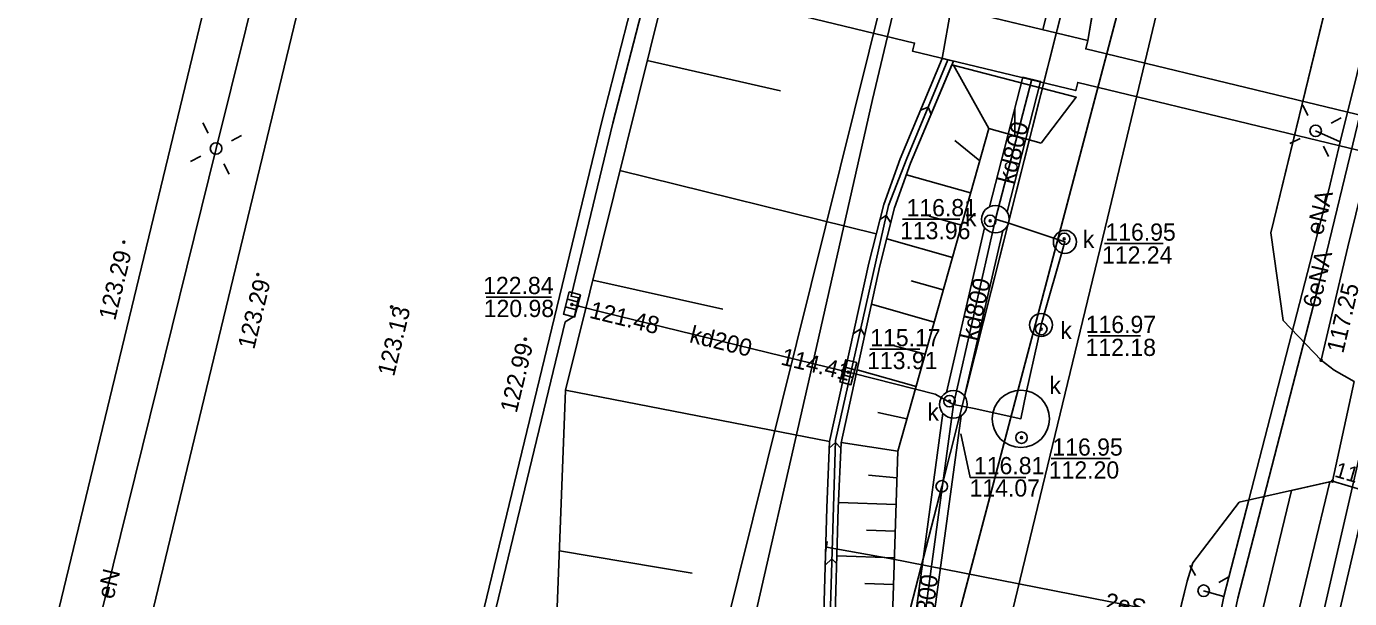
# Model space of a CAD drawing. Extents: x 6424617 to 6425697, y 5665845 to 5667190.
# Drawn here: x 6425313.5 to 6425371.2, y 5666362.7 to 5666387.6 of the extents above; entities that cross this region are included whole.
import ezdxf

# ---------------------------------------------------------------- set-up
doc = ezdxf.new("R2010")
doc.units = 0
for name, color, linetype in [('Warstwa 1', 7, 'Continuous'), ('Warstwa 10', 7, 'Continuous'), ('Warstwa 11', 7, 'Continuous'), ('Warstwa 12', 7, 'Continuous'), ('Warstwa 13', 7, 'Continuous'), ('Warstwa 14', 7, 'Continuous'), ('Warstwa 15', 7, 'Continuous'), ('Warstwa 16', 7, 'Continuous'), ('Warstwa 2', 7, 'Continuous'), ('Warstwa 20', 7, 'Continuous'), ('Warstwa 21', 7, 'Continuous'), ('Warstwa 22', 7, 'Continuous'), ('Warstwa 25', 7, 'Continuous'), ('Warstwa 4', 7, 'Continuous'), ('Warstwa 5', 7, 'Continuous'), ('Warstwa 6', 7, 'Continuous'), ('Warstwa 61', 7, 'Continuous'), ('Warstwa 8', 7, 'Continuous'), ('Warstwa 9', 7, 'Continuous')]:
    doc.layers.add(name, color=color, linetype=linetype)

msp = doc.modelspace()

# ---------------------------------------------------------------- linework, layer by layer
at = {"layer": 'Warstwa 1'}
for p, q in [((6425353.441, 5666367.596), (6425363.818, 5666408.694)), ((6425353.441, 5666367.596), (6425363.818, 5666408.694)), ((6425352.06, 5666353.98), (6425364.93, 5666402.71)), ((6425352.06, 5666353.98), (6425364.93, 5666402.71)), ((6425328.388, 5666270.5), (6425353.441, 5666367.596)), ((6425328.388, 5666270.5), (6425353.441, 5666367.596))]:
    msp.add_line(p, q, dxfattribs=at)
at = {"layer": 'Warstwa 10'}
msp.add_lwpolyline([(6425441.845, 5666345.034), (6425435.644, 5666345.684), (6425416.754, 5666350.792), (6425414.426, 5666349.31), (6425409.689, 5666350.497), (6425397.042, 5666354.07), (6425390.053, 5666355.924), (6425382.597, 5666357.904), (6425376.603, 5666359.336), (6425374.869, 5666359.807), (6425368.783, 5666361.001), (6425351.183, 5666364.453), (6425348.415, 5666364.948)], dxfattribs=at)
msp.add_circle((6425353.441, 5666367.596), 0.25, dxfattribs=at)
msp.add_circle((6425353.441, 5666367.596), 0.25, dxfattribs=at)
at = {"layer": 'Warstwa 12'}
for points in [[(6425398.761, 5666563.583), (6425397.55, 5666559.5), (6425397.03, 5666557.16), (6425392.45, 5666536.96), (6425386, 5666508.09), (6425382.01, 5666490.27), (6425381.21, 5666479.99), (6425379.9, 5666475.3), (6425381.52, 5666474.89), (6425375.93, 5666454.14), (6425373.99, 5666454.38), (6425373.44, 5666451.82), (6425375.23, 5666451.4), (6425362.43, 5666401.17), (6425355.8, 5666402.66), (6425355.08, 5666402.04), (6425351.66, 5666389.66), (6425350.42, 5666384.46), (6425347.89, 5666373.29), (6425344.69, 5666359.22), (6425346.02, 5666355.28), (6425340.77, 5666330.04), (6425337.023, 5666314.31)], [(6425305.48, 5666314.773), (6425311.14, 5666338.26), (6425315.72, 5666356.59), (6425314.85, 5666358.59), (6425315.59, 5666360.88), (6425316.68, 5666361.57), (6425321.81, 5666382.32), (6425327.66, 5666405.82), (6425332.54, 5666426.33), (6425338.92, 5666452.89), (6425344.68, 5666476.52), (6425348.06, 5666490.52), (6425353.32, 5666512.48), (6425356.9, 5666527.18)], [(6425366.353, 5666362.72), (6425369.879, 5666376.399), (6425373.51, 5666391.396), (6425377.162, 5666406.423), (6425378.544, 5666412.437), (6425386.549, 5666444.283), (6425388.297, 5666450.692), (6425392.281, 5666465.105), (6425394.427, 5666468.919), (6425394.601, 5666469.247), (6425394.673, 5666469.407), (6425394.808, 5666469.795), (6425394.976, 5666470.533), (6425395.345, 5666472.079), (6425395.789, 5666472.383), (6425396.66, 5666472.55), (6425396.753, 5666472.692)], [(6425357.852, 5666387.491), (6425359.23, 5666393.09)], [(6425372.286, 5666388.56), (6425370.814, 5666382.608), (6425370.308, 5666380.514), (6425366.825, 5666367.005), (6425365.734, 5666362.797), (6425363.15, 5666350.048), (6425362.095, 5666344.63), (6425362.071, 5666344.32), (6425362.257, 5666343.998), (6425365.292, 5666341.111), (6425367.972, 5666338.599), (6425368.306, 5666338.48)], [(6425355.522, 5666379.782), (6425356.973, 5666385.427), (6425357.751, 5666385.24), (6425356.289, 5666379.557)], [(6425369.739, 5666383.091), (6425370.814, 5666382.608)], [(6425353.95, 5666371.17), (6425354.85, 5666370.99), (6425356.89, 5666370.54), (6425357.12, 5666371.67), (6425357.63, 5666373.94), (6425357.77, 5666374.63), (6425357.97, 5666375.3), (6425358.62, 5666377.58), (6425358.81, 5666378.25), (6425358.15, 5666378.47), (6425356.45, 5666379.04), (6425355.78, 5666379.24)], [(6425353.651, 5666371.69), (6425355.31, 5666378.867)], [(6425356.101, 5666378.733), (6425354.435, 5666371.523)], [(6425337.32, 5666375.52), (6425337.57, 5666375.46), (6425338.72, 5666375.17), (6425349.12, 5666372.63), (6425349.37, 5666372.57), (6425349.61, 5666372.51), (6425353.15, 5666371.62), (6425353.95, 5666371.17)], [(6425362.024, 5666327.189), (6425372.889, 5666374.253)], [(6425351.71, 5666357.654), (6425353.494, 5666370.78)], [(6425354.286, 5666370.673), (6425352.503, 5666357.553)], [(6425365.734, 5666362.797), (6425364.857, 5666363.048)], [(6425368.46, 5666338.433), (6425362.583, 5666344.464), (6425364.475, 5666353.762), (6425366.353, 5666362.72)]]:
    msp.add_lwpolyline(points, dxfattribs=at)
at = {"layer": 'Warstwa 14'}
for p, q in [((6425354.229, 5666379.242), (6425351.726, 5666379.242)), ((6425363.087, 5666378.178), (6425360.53, 5666378.178)), ((6425336.427, 5666375.838), (6425333.589, 5666375.838)), ((6425362.109, 5666374.154), (6425359.818, 5666374.154)), ((6425352.486, 5666373.58), (6425350.305, 5666373.58)), ((6425360.788, 5666368.81), (6425358.208, 5666368.81))]:
    msp.add_line(p, q, dxfattribs=at)
msp.add_lwpolyline([(6425357.102, 5666367.98), (6425354.687, 5666367.98), (6425354.278, 5666369.881)], dxfattribs=at)
for centre in [(6425355.55, 5666379.17), (6425358.78, 5666378.38), (6425337.32, 5666375.52), (6425337.57, 5666375.46), (6425357.78, 5666374.45), (6425349.12, 5666372.63), (6425349.37, 5666372.57), (6425353.78, 5666371.31), (6425356.92, 5666369.72)]:
    msp.add_circle(centre, 0.045, dxfattribs=at)
at = {"layer": 'Warstwa 16'}
for centre, radius in [((6425355.78, 5666379.24), 0.6), ((6425358.81, 5666378.25), 0.5), ((6425357.77, 5666374.63), 0.5), ((6425353.95, 5666371.17), 0.6), ((6425356.89, 5666370.54), 1.25)]:
    msp.add_circle(centre, radius, dxfattribs=at)
at = {"layer": 'Warstwa 2'}
msp.add_lwpolyline([(6425342.431, 5666314.245), (6425342.9, 5666316.26), (6425351.432, 5666353.898), (6425342.677, 5666355.997), (6425354.705, 5666404.396), (6425364.488, 5666402.728), (6425382.828, 5666478.302), (6425401.605, 5666563.549)], dxfattribs=at)
for centre in [(6425369.739, 5666383.091), (6425321.81, 5666382.32), (6425364.857, 5666363.048)]:
    msp.add_circle(centre, 0.25, dxfattribs=at)
at = {"layer": 'Warstwa 20'}
msp.add_line((6425348.38, 5666364.7), (6425348.45, 5666365.196), dxfattribs=at)
for points in [[(6425326.04, 5666314.442), (6425336.507, 5666357.769), (6425337.041, 5666371.794), (6425341.788, 5666390.934), (6425346.79, 5666410.35), (6425362.358, 5666467.618), (6425366.796, 5666476.821), (6425368.004, 5666481.671), (6425368.42, 5666492.007), (6425372.53, 5666509.068), (6425385.231, 5666561.556), (6425385.761, 5666563.74)], [(6425357.772, 5666382.553), (6425355.492, 5666383.194), (6425351.527, 5666369.131), (6425351.075, 5666355.185), (6425350.421, 5666351.646), (6425344.982, 5666329.077), (6425341.427, 5666314.257)]]:
    msp.add_lwpolyline(points, dxfattribs=at)
at = {"layer": 'Warstwa 21'}
for points in [[(6425338.781, 5666314.289), (6425342.093, 5666328.629), (6425347.916, 5666354.162), (6425348.109, 5666355.419), (6425348.432, 5666366.657), (6425348.554, 5666369.545), (6425350.265, 5666377.317), (6425350.911, 5666379.876), (6425351.627, 5666381.874), (6425353.464, 5666386.247), (6425353.858, 5666388.451), (6425354.565, 5666392.214), (6425355.215, 5666394.983), (6425357.587, 5666405.034), (6425362.218, 5666424.397), (6425369.236, 5666451.879), (6425372.67, 5666465.301), (6425376.112, 5666474.212), (6425378.491, 5666484.102), (6425377.911, 5666489.644), (6425387.002, 5666528.883), (6425394.525, 5666561.078), (6425395.128, 5666563.627)], [(6425359.81, 5666387.02), (6425354.35, 5666388.333), (6425355.063, 5666392.105), (6425355.693, 5666394.875), (6425357.414, 5666402.106), (6425358.065, 5666404.925), (6425362.696, 5666424.268), (6425369.714, 5666451.75), (6425373.147, 5666465.152), (6425376.589, 5666474.063), (6425378.991, 5666484.073), (6425378.41, 5666489.615), (6425387.48, 5666528.774), (6425395.003, 5666560.949), (6425395.635, 5666563.62)], [(6425339.288, 5666314.283), (6425342.571, 5666328.52), (6425348.415, 5666354.073), (6425348.608, 5666355.37), (6425348.932, 5666366.648), (6425349.053, 5666369.496), (6425350.743, 5666377.208), (6425351.388, 5666379.727), (6425352.084, 5666381.686), (6425353.882, 5666385.964), (6425359.308, 5666384.556)]]:
    msp.add_lwpolyline(points, dxfattribs=at)
at = {"layer": 'Warstwa 22'}
msp.add_lwpolyline([(6425352.7, 5666388.73), (6425359.81, 5666387.02), (6425359.721, 5666386.659), (6425384.611, 5666380.644), (6425384.259, 5666379.186), (6425359.369, 5666385.201), (6425359.28, 5666384.84), (6425352.17, 5666386.56), (6425352.257, 5666386.916), (6425297.227, 5666400.216), (6425297.583, 5666401.674), (6425352.613, 5666388.374), (6425352.7, 5666388.73)], dxfattribs=at)
at = {"layer": 'Warstwa 25'}
for centre in [(6425317.791, 5666378.234), (6425323.627, 5666376.828), (6425329.464, 5666375.412), (6425335.29, 5666374.006), (6425369.98, 5666373.09), (6425370.47, 5666367.82)]:
    msp.add_circle(centre, 0.045, dxfattribs=at)
at = {"layer": 'Warstwa 4'}
for p, q in [((6425337.607, 5666375.624), (6425337.124, 5666375.754)), ((6425337.516, 5666375.286), (6425337.033, 5666375.416)), ((6425349.656, 5666372.676), (6425349.173, 5666372.803)), ((6425349.567, 5666372.337), (6425349.084, 5666372.464))]:
    msp.add_line(p, q, dxfattribs=at)
for points in [[(6425369.403, 5666383.762), (6425369.179, 5666384.209)], [(6425321.469, 5666382.988), (6425321.241, 5666383.433)], [(6425370.41, 5666383.427), (6425370.857, 5666383.651)], [(6425322.478, 5666382.661), (6425322.923, 5666382.889)], [(6425369.068, 5666382.755), (6425368.621, 5666382.531)], [(6425370.075, 5666382.42), (6425370.299, 5666381.973)], [(6425321.142, 5666381.979), (6425320.697, 5666381.751)], [(6425322.151, 5666381.652), (6425322.379, 5666381.207)], [(6425364.497, 5666363.706), (6425364.256, 5666364.144)], [(6425365.515, 5666363.408), (6425365.953, 5666363.649)]]:
    msp.add_lwpolyline(points, dxfattribs=at)
for points in [[(6425337.692, 5666375.938), (6425337.431, 5666374.972), (6425336.948, 5666375.102), (6425337.209, 5666376.068)], [(6425349.739, 5666372.99), (6425349.485, 5666372.023), (6425349.001, 5666372.15), (6425349.255, 5666373.117)]]:
    msp.add_lwpolyline(points, close=True, dxfattribs=at)
for centre in [(6425355.55, 5666379.17), (6425358.78, 5666378.38), (6425357.78, 5666374.45), (6425353.78, 5666371.31), (6425356.92, 5666369.72)]:
    msp.add_circle(centre, 0.25, dxfattribs=at)
at = {"layer": 'Warstwa 5'}
for p, q in [((6425364.91, 5666345.22), (6425370.351, 5666367.793)), ((6425370.351, 5666367.793), (6425370.47, 5666367.82)), ((6425370.47, 5666367.82), (6425381.83, 5666364.46))]:
    msp.add_line(p, q, dxfattribs=at)
at = {"layer": 'Warstwa 6'}
for points in [[(6425305.245, 5666173.41), (6425312.278, 5666201.804), (6425314.518, 5666211.716), (6425317.57, 5666225.189), (6425322.489, 5666245.769), (6425323.828, 5666251.474), (6425324.47, 5666254.176), (6425328.388, 5666270.5), (6425353.441, 5666367.596), (6425363.818, 5666408.694)], [(6425363.818, 5666408.694), (6425353.441, 5666367.596), (6425328.388, 5666270.5), (6425324.47, 5666254.176), (6425323.828, 5666251.474), (6425322.489, 5666245.769), (6425317.57, 5666225.189), (6425314.518, 5666211.716), (6425312.278, 5666201.804), (6425305.245, 5666173.41)], [(6425306.64, 5666159.22), (6425325.89, 5666241.74), (6425352.06, 5666353.98), (6425364.93, 5666402.71)], [(6425364.93, 5666402.71), (6425352.06, 5666353.98), (6425325.89, 5666241.74), (6425306.64, 5666159.22)], [(6425324.645, 5666325.693), (6425325.123, 5666325.574), (6425330.41, 5666347.476), (6425330.825, 5666347.738), (6425331.029, 5666348.525), (6425330.71, 5666348.611), (6425337.034, 5666374.765), (6425337.439, 5666375.018), (6425337.613, 5666375.815), (6425337.285, 5666375.881), (6425339.111, 5666383.43), (6425343.866, 5666401.89)], [(6425372.03, 5666396.08), (6425367.79, 5666378.65), (6425368.33, 5666374.83), (6425369.98, 5666373.09), (6425370.55, 5666372.66), (6425371.42, 5666372.17)], [(6425370.47, 5666367.82), (6425366.41, 5666366.91), (6425364.38, 5666364.26), (6425364.14, 5666363.47), (6425363.41, 5666360.47)]]:
    msp.add_lwpolyline(points, dxfattribs=at)
at = {"layer": 'Warstwa 61'}
for points in [[(6425385.173, 5666423.021), (6425373.736, 5666374.755), (6425362.341, 5666326.087), (6425359.463, 5666314.04)], [(6425341.704, 5666314.254), (6425342.827, 5666318.91), (6425348.934, 5666344.24), (6425352.05, 5666357.16), (6425353.95, 5666371.17), (6425355.78, 5666379.24), (6425357.362, 5666385.334)]]:
    msp.add_lwpolyline(points, dxfattribs=at)
at = {"layer": 'Warstwa 8'}
for p, q in [((6425306.044, 5666325.418), (6425357.544, 5666538.388)), ((6425309.895, 5666324.328), (6425361.428, 5666537.448)), ((6425338.634, 5666383.559), (6425363.59, 5666480.42)), ((6425360.66, 5666379.29), (6425365.23, 5666398.34)), ((6425367.79, 5666378.65), (6425372.03, 5666396.08)), ((6425324.645, 5666325.693), (6425338.634, 5666383.559)), ((6425356.42, 5666361.75), (6425360.66, 5666379.29)), ((6425367.79, 5666378.65), (6425368.33, 5666374.83)), ((6425368.33, 5666374.83), (6425369.98, 5666373.09)), ((6425369.98, 5666373.09), (6425370.55, 5666372.66)), ((6425370.55, 5666372.66), (6425371.42, 5666372.17)), ((6425370.47, 5666367.82), (6425371.42, 5666372.17)), ((6425370.47, 5666367.82), (6425371.42, 5666372.17)), ((6425366.41, 5666366.91), (6425370.47, 5666367.82)), ((6425370.47, 5666367.82), (6425381.83, 5666364.46)), ((6425364.38, 5666364.26), (6425366.41, 5666366.91)), ((6425364.14, 5666363.47), (6425364.38, 5666364.26)), ((6425360.91, 5666350.31), (6425364.14, 5666363.47))]:
    msp.add_line(p, q, dxfattribs=at)
msp.add_lwpolyline([(6425373.51, 5666391.396), (6425369.879, 5666376.399), (6425366.353, 5666362.72), (6425364.475, 5666353.762), (6425362.583, 5666344.464), (6425368.46, 5666338.433)], dxfattribs=at)
at = {"layer": 'Warstwa 9'}
for p, q in [((6425371.14, 5666378.03), (6425383.354, 5666428.11)), ((6425360.227, 5666389.481), (6425359.81, 5666387.02)), ((6425340.601, 5666386.149), (6425346.411, 5666384.834)), ((6425351.924, 5666381.884), (6425353.708, 5666386.188)), ((6425355.492, 5666383.194), (6425353.949, 5666385.946)), ((6425357.772, 5666382.553), (6425359.308, 5666384.556)), ((6425352.514, 5666383.985), (6425352.853, 5666384.125)), ((6425352.98, 5666383.818), (6425352.853, 5666384.125)), ((6425356.632, 5666382.874), (6425356.63, 5666384.062)), ((6425355.096, 5666381.788), (6425354.01, 5666382.673)), ((6425351.123, 5666379.833), (6425351.924, 5666381.884)), ((6425339.414, 5666381.364), (6425350.587, 5666378.594)), ((6425354.699, 5666380.381), (6425351.901, 5666381.171)), ((6425348.81, 5666369.596), (6425351.123, 5666379.833)), ((6425350.747, 5666379.226), (6425351.026, 5666379.402)), ((6425351.224, 5666379.087), (6425351.026, 5666379.402)), ((6425354.302, 5666378.975), (6425352.887, 5666379.374)), ((6425353.906, 5666377.569), (6425351.042, 5666378.377)), ((6425369.98, 5666373.09), (6425371.14, 5666378.03)), ((6425338.228, 5666376.579), (6425343.899, 5666375.324)), ((6425353.51, 5666376.162), (6425352.109, 5666376.558)), ((6425353.113, 5666374.756), (6425350.375, 5666375.529)), ((6425349.591, 5666374.256), (6425349.908, 5666374.456)), ((6425350.08, 5666374.184), (6425349.908, 5666374.456)), ((6425352.716, 5666373.35), (6425351.389, 5666373.725)), ((6425369.98, 5666373.09), (6425370.55, 5666372.66)), ((6425352.32, 5666371.944), (6425349.749, 5666372.67)), ((6425370.55, 5666372.66), (6425371.42, 5666372.17)), ((6425337.041, 5666371.794), (6425348.554, 5666369.545)), ((6425351.924, 5666370.538), (6425350.663, 5666370.814)), ((6425348.396, 5666355.968), (6425348.81, 5666369.596)), ((6425348.542, 5666369.258), (6425348.808, 5666369.508)), ((6425349.043, 5666369.258), (6425348.808, 5666369.508)), ((6425351.527, 5666369.131), (6425349.057, 5666369.513)), ((6425351.489, 5666367.969), (6425350.244, 5666368.085)), ((6425364.91, 5666345.22), (6425370.351, 5666367.793)), ((6425368.683, 5666367.42), (6425370.351, 5666367.793)), ((6425363.42, 5666345.6), (6425368.683, 5666367.42)), ((6425351.452, 5666366.807), (6425348.942, 5666366.889)), ((6425351.414, 5666365.644), (6425350.16, 5666365.686)), ((6425336.774, 5666364.782), (6425342.558, 5666363.816)), ((6425348.36, 5666364.164), (6425348.653, 5666364.44)), ((6425348.862, 5666364.218), (6425348.653, 5666364.44)), ((6425351.376, 5666364.482), (6425348.872, 5666364.564)), ((6425351.339, 5666363.32), (6425350.089, 5666363.361))]:
    msp.add_line(p, q, dxfattribs=at)
for points in [[(6425341.788, 5666390.934), (6425337.041, 5666371.794), (6425336.507, 5666357.769), (6425326.04, 5666314.442), (6425338.781, 5666314.289), (6425342.093, 5666328.629), (6425347.916, 5666354.162), (6425348.109, 5666355.419), (6425348.432, 5666366.657), (6425348.554, 5666369.545), (6425350.265, 5666377.317), (6425350.911, 5666379.876), (6425351.627, 5666381.874), (6425353.464, 5666386.247), (6425353.858, 5666388.451)], [(6425354.35, 5666388.333), (6425359.81, 5666387.02), (6425360.227, 5666389.481)]]:
    msp.add_lwpolyline(points, dxfattribs=at)
for points in [[(6425338.781, 5666314.289), (6425342.093, 5666328.629), (6425347.916, 5666354.162), (6425348.109, 5666355.419), (6425348.432, 5666366.657), (6425348.554, 5666369.545), (6425350.265, 5666377.317), (6425350.911, 5666379.876), (6425351.627, 5666381.874), (6425353.464, 5666386.247), (6425353.951, 5666386.129), (6425352.084, 5666381.686), (6425351.388, 5666379.727), (6425350.743, 5666377.208), (6425349.053, 5666369.496), (6425348.932, 5666366.648), (6425348.608, 5666355.37), (6425348.415, 5666354.073), (6425342.571, 5666328.52), (6425339.288, 5666314.283)], [(6425357.772, 5666382.553), (6425355.492, 5666383.194), (6425351.527, 5666369.131), (6425351.075, 5666355.185), (6425350.421, 5666351.646), (6425344.982, 5666329.077), (6425341.427, 5666314.257), (6425339.288, 5666314.283), (6425342.571, 5666328.52), (6425348.415, 5666354.073), (6425348.608, 5666355.37), (6425348.932, 5666366.648), (6425349.053, 5666369.496), (6425350.743, 5666377.208), (6425351.388, 5666379.727), (6425352.084, 5666381.686), (6425353.882, 5666385.964), (6425359.308, 5666384.556)]]:
    msp.add_lwpolyline(points, close=True, dxfattribs=at)

# ---------------------------------------------------------------- texts
at = {"layer": 'Warstwa 11'}
msp.add_text('2eS', height=0.75, rotation=349.5902, dxfattribs=at).set_placement((6425360.514, 5666362.229))
at = {"layer": 'Warstwa 13'}
for s, rotation, p in [('kd800', 75.57313, (6425356.564, 5666380.726)), ('eNA', 76.23203, (6425370.035, 5666378.501)), ('6eNA', 76.91385, (6425369.9, 5666375.327)), ('kd800', 76.98834, (6425354.96, 5666373.906)), ('kd200', 346.27277, (6425342.406, 5666373.884)), ('eN', 76.11171, (6425317.331, 5666362.641)), ('kd800', 82.25955, (6425352.921, 5666360.993))]:
    msp.add_text(s, height=0.75, rotation=rotation, dxfattribs=at).set_placement(p)
at = {"layer": 'Warstwa 14'}
for s, p in [('113.96', (6425351.626, 5666378.367)), ('112.24', (6425360.43, 5666377.303)), ('120.98', (6425333.478, 5666374.975)), ('112.18', (6425359.712, 5666373.279)), ('113.91', (6425350.19, 5666372.704)), ('112.20', (6425358.108, 5666367.935)), ('114.07', (6425354.656, 5666367.15))]:
    msp.add_text(s, height=0.75, dxfattribs=at).set_placement(p)
for s, p in [('121.48', (6425338.044, 5666374.949)), ('114.41', (6425346.385, 5666372.912))]:
    msp.add_text(s, height=0.75, rotation=346.27277, dxfattribs=at).set_placement(p)
at = {"layer": 'Warstwa 15'}
for s, p in [('116.81', (6425351.906, 5666379.367)), ('116.95', (6425360.575, 5666378.303)), ('122.84', (6425333.453, 5666375.976)), ('116.97', (6425359.717, 5666374.279)), ('115.17', (6425350.325, 5666373.704)), ('116.95', (6425358.264, 5666368.935)), ('116.81', (6425354.846, 5666368.126))]:
    msp.add_text(s, height=0.75, dxfattribs=at).set_placement(p)
at = {"layer": 'Warstwa 25'}
for s, height, rotation, p in [('123.29', 0.75, 76.40392, (6425317.41, 5666374.793)), ('123.29', 0.75, 76.40392, (6425323.47, 5666373.531)), ('117.25', 0.75, 76.7878, (6425370.94, 5666373.362)), ('123.13', 0.75, 76.40392, (6425329.565, 5666372.352)), ('122.99', 0.75, 76.40392, (6425334.91, 5666370.758)), ('117.17', 0.6769, 343.61425, (6425370.526, 5666368.024))]:
    msp.add_text(s, height=height, rotation=rotation, dxfattribs=at).set_placement(p)
at = {"layer": 'Warstwa 5'}
for p in [(6425354.454, 5666378.935), (6425359.591, 5666377.987), (6425358.609, 5666374.018), (6425358.136, 5666371.624), (6425352.813, 5666370.466)]:
    msp.add_text('k', height=0.75, dxfattribs=at).set_placement(p)

doc.saveas('drawing.dxf')
